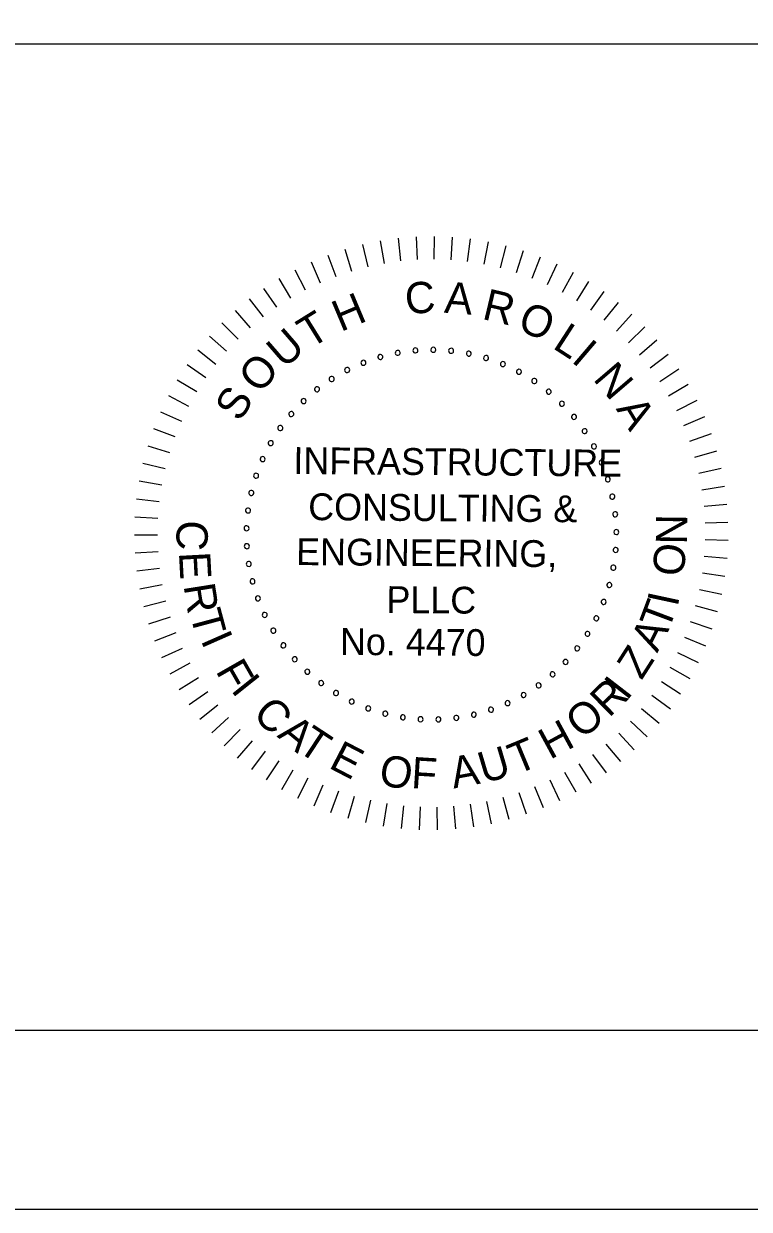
# Model space of a CAD drawing. Extents: x -133.1 to -97, y -110.1 to -88.1.
# Drawn here: x -107.945 to -105.922, y -110.103 to -106.796 of the extents above; entities that cross this region are included whole.
import ezdxf

# ---------------------------------------------------------------- set-up
doc = ezdxf.new("R2010")
doc.units = 0
for name, color, linetype in [('BR_BORDER LINES', 7, 'Continuous'), ('BR_TEXT', 7, 'Continuous'), ('Level 31', 7, 'Continuous')]:
    doc.layers.add(name, color=color, linetype=linetype)

msp = doc.modelspace()

# ---------------------------------------------------------------- linework, layer by layer
at = {"layer": 'BR_BORDER LINES'}
for p, q in [((-110.5071, -106.8526), (-105.1419, -106.8526)), ((-131.3076, -109.6027), (-97.6416, -109.6027))]:
    msp.add_line(p, q, dxfattribs=at)
at = {"layer": 'BR_TEXT'}
for p, q in [((-106.9012, -107.3945), (-106.894, -107.4577)), ((-106.8509, -107.3903), (-106.8476, -107.4539)), ((-106.8005, -107.3893), (-106.801, -107.4529)), ((-106.75, -107.3913), (-106.7544, -107.4548)), ((-106.6998, -107.3964), (-106.7081, -107.4595)), ((-107.0494, -107.4251), (-107.0308, -107.486)), ((-107.0007, -107.4119), (-106.9858, -107.4738)), ((-106.9512, -107.4017), (-106.9401, -107.4644)), ((-106.65, -107.4045), (-106.6621, -107.467)), ((-106.6007, -107.4157), (-106.6166, -107.4773)), ((-106.5523, -107.4298), (-106.5719, -107.4904)), ((-107.1439, -107.4603), (-107.1181, -107.5185)), ((-107.0972, -107.4413), (-107.0749, -107.5009)), ((-106.5048, -107.4469), (-106.528, -107.5062)), ((-107.1895, -107.4822), (-107.1601, -107.5387)), ((-106.4584, -107.4668), (-106.4852, -107.5246)), ((-106.4133, -107.4896), (-106.4436, -107.5456)), ((-107.2335, -107.5068), (-107.2008, -107.5614)), ((-106.3697, -107.515), (-106.4034, -107.569)), ((-107.276, -107.5341), (-107.24, -107.5865)), ((-106.3277, -107.543), (-106.3646, -107.5949)), ((-107.3557, -107.5961), (-107.3135, -107.6438)), ((-107.3168, -107.5638), (-107.2776, -107.614)), ((-106.2875, -107.5736), (-106.3275, -107.6231)), ((-106.2493, -107.6065), (-106.2922, -107.6535)), ((-107.3925, -107.6306), (-107.3475, -107.6756)), ((-106.2131, -107.6418), (-106.2588, -107.6861)), ((-107.4272, -107.6673), (-107.3795, -107.7095)), ((-106.1791, -107.6791), (-106.2275, -107.7205)), ((-107.4595, -107.706), (-107.4094, -107.7453)), ((-106.1475, -107.7185), (-106.1983, -107.7569)), ((-107.4895, -107.7467), (-107.437, -107.7828)), ((-106.1184, -107.7597), (-106.1714, -107.7949)), ((-107.5169, -107.7891), (-107.4623, -107.8219)), ((-106.0918, -107.8026), (-106.1469, -107.8345)), ((-107.5416, -107.8331), (-107.4852, -107.8625)), ((-106.0679, -107.847), (-106.1248, -107.8756)), ((-107.5637, -107.8785), (-107.5055, -107.9045)), ((-106.0467, -107.8929), (-106.1052, -107.9179)), ((-107.5829, -107.9252), (-107.5233, -107.9475)), ((-106.0283, -107.9399), (-106.0883, -107.9613)), ((-107.5992, -107.9729), (-107.5384, -107.9916)), ((-106.0129, -107.988), (-106.0741, -108.0057)), ((-107.6126, -108.0216), (-107.5507, -108.0366)), ((-106.0004, -108.0369), (-106.0625, -108.0508)), ((-107.623, -108.071), (-107.5604, -108.0822)), ((-105.9909, -108.0865), (-106.0538, -108.0966)), ((-107.6304, -108.121), (-107.5672, -108.1283)), ((-105.9845, -108.1366), (-106.0479, -108.1428)), ((-107.6348, -108.1712), (-107.5712, -108.1747)), ((-105.9811, -108.1869), (-106.0448, -108.1893)), ((-107.636, -108.2217), (-107.5723, -108.2213)), ((-105.9809, -108.2374), (-106.0445, -108.2359)), ((-107.6342, -108.2722), (-107.5706, -108.2678)), ((-105.9836, -108.2878), (-106.0471, -108.2824)), ((-107.6293, -108.3224), (-107.5661, -108.3142)), ((-105.9895, -108.338), (-106.0525, -108.3287)), ((-107.6213, -108.3723), (-107.5588, -108.3602)), ((-105.9984, -108.3876), (-106.0607, -108.3746)), ((-107.6103, -108.4215), (-107.5487, -108.4057)), ((-106.0103, -108.4367), (-106.0717, -108.4199)), ((-107.5964, -108.4701), (-107.5358, -108.4505)), ((-106.0252, -108.4849), (-106.0855, -108.4644)), ((-107.5795, -108.5176), (-107.5202, -108.4944)), ((-106.043, -108.5322), (-106.1019, -108.508)), ((-107.5597, -108.5641), (-107.5019, -108.5373)), ((-106.0636, -108.5783), (-106.1209, -108.5505)), ((-107.5371, -108.6092), (-107.4811, -108.579)), ((-107.5119, -108.6529), (-107.4578, -108.6193)), ((-106.087, -108.623), (-106.1426, -108.5918)), ((-106.1131, -108.6662), (-106.1667, -108.6317)), ((-107.484, -108.695), (-107.4321, -108.6582)), ((-106.1418, -108.7077), (-106.1931, -108.6701)), ((-107.4536, -108.7353), (-107.404, -108.6954)), ((-106.173, -108.7475), (-106.2219, -108.7067)), ((-107.4208, -108.7737), (-107.3737, -108.7308)), ((-106.2065, -108.7852), (-106.2529, -108.7416)), ((-107.3857, -108.81), (-107.3413, -108.7643)), ((-106.2423, -108.8208), (-106.2859, -108.7744)), ((-107.3485, -108.8441), (-107.307, -108.7958)), ((-106.2801, -108.8542), (-106.3208, -108.8053)), ((-107.3092, -108.8759), (-107.2708, -108.8251)), ((-107.2681, -108.9052), (-107.2328, -108.8522)), ((-106.32, -108.8852), (-106.3576, -108.8339)), ((-107.2253, -108.9319), (-107.1933, -108.8769)), ((-106.4049, -108.9397), (-106.436, -108.8841)), ((-106.3616, -108.9138), (-106.3961, -108.8602)), ((-107.1809, -108.956), (-107.1523, -108.8991)), ((-107.1352, -108.9774), (-107.1101, -108.9188)), ((-106.4498, -108.963), (-106.4774, -108.9056)), ((-107.0882, -108.9959), (-107.0668, -108.9359)), ((-107.0402, -109.0115), (-107.0225, -108.9504)), ((-106.5432, -109.001), (-106.5637, -108.9408)), ((-106.4959, -108.9834), (-106.52, -108.9245)), ((-106.9913, -109.0242), (-106.9773, -108.962)), ((-106.9418, -109.0338), (-106.9316, -108.971)), ((-106.8918, -109.0404), (-106.8854, -108.9771)), ((-106.8414, -109.044), (-106.8389, -108.9804)), ((-106.7909, -109.0445), (-106.7923, -108.9808)), ((-106.7405, -109.0419), (-106.7458, -108.9784)), ((-106.6903, -109.0362), (-106.6995, -108.9732)), ((-106.6406, -109.0275), (-106.6536, -108.9651)), ((-106.5915, -109.0157), (-106.6083, -108.9543))]:
    msp.add_line(p, q, dxfattribs=at)
for centre, start, end in [((-106.9506, -107.7254), 16.1422, 196.1422), ((-106.9506, -107.7254), 196.1422, 16.1422), ((-106.9021, -107.714), 10.6038, 190.6038), ((-106.9021, -107.714), 190.6038, 10.6038), ((-106.8527, -107.7073), 5.0653, 185.0653), ((-106.8527, -107.7073), 185.0653, 5.0653), ((-106.8029, -107.7054), 359.5268, 179.5268), ((-106.8029, -107.7054), 179.5268, 359.5268), ((-106.7531, -107.7083), 173.9884, 353.9884), ((-106.7531, -107.7083), 353.9884, 173.9884), ((-106.7039, -107.716), 168.4499, 348.4499), ((-106.7039, -107.716), 348.4499, 168.4499), ((-106.6557, -107.7285), 162.9114, 342.9114), ((-106.6557, -107.7285), 342.9114, 162.9114), ((-107.0431, -107.762), 27.2191, 207.2191), ((-107.0431, -107.762), 207.2191, 27.2191), ((-106.9977, -107.7415), 21.6807, 201.6807), ((-106.9977, -107.7415), 201.6807, 21.6807), ((-106.6088, -107.7455), 157.373, 337.373), ((-106.6088, -107.7455), 337.373, 157.373), ((-106.5639, -107.7669), 331.8345, 151.8345), ((-107.0864, -107.7869), 32.7576, 212.7576), ((-107.0864, -107.7869), 212.7576, 32.7576), ((-106.5639, -107.7669), 151.8345, 331.8345), ((-106.5212, -107.7926), 146.2961, 326.2961), ((-106.5212, -107.7926), 326.2961, 146.2961), ((-107.127, -107.8157), 38.2961, 218.2961), ((-107.127, -107.8157), 218.2961, 38.2961), ((-106.4811, -107.8223), 140.7576, 320.7576), ((-106.4811, -107.8223), 320.7576, 140.7576), ((-107.1646, -107.8484), 43.8345, 223.8345), ((-107.1646, -107.8484), 223.8345, 43.8345), ((-106.4442, -107.8558), 135.2191, 315.2191), ((-106.4442, -107.8558), 315.2191, 135.2191), ((-107.1989, -107.8845), 49.373, 229.373), ((-107.1989, -107.8845), 229.373, 49.373), ((-106.4106, -107.8926), 129.6807, 309.6807), ((-106.4106, -107.8926), 309.6807, 129.6807), ((-107.2296, -107.9238), 54.9114, 234.9114), ((-107.2296, -107.9238), 234.9114, 54.9114), ((-106.3808, -107.9325), 124.1422, 304.1422), ((-106.3808, -107.9325), 304.1422, 124.1422), ((-107.2563, -107.9659), 60.4499, 240.4499), ((-107.2563, -107.9659), 240.4499, 60.4499), ((-106.3549, -107.9751), 118.6038, 298.6038), ((-106.3549, -107.9751), 298.6038, 118.6038), ((-107.2788, -108.0103), 65.9884, 245.9884), ((-107.2788, -108.0103), 245.9884, 65.9884), ((-106.3333, -108.02), 113.0653, 293.0653), ((-106.3333, -108.02), 293.0653, 113.0653), ((-107.297, -108.0567), 71.5268, 251.5268), ((-107.297, -108.0567), 251.5268, 71.5268), ((-106.3161, -108.0668), 107.5268, 287.5268), ((-106.3161, -108.0668), 287.5268, 107.5268), ((-107.3106, -108.1047), 77.0653, 257.0653), ((-107.3106, -108.1047), 257.0653, 77.0653), ((-106.3035, -108.115), 101.9884, 281.9884), ((-106.3035, -108.115), 281.9884, 101.9884), ((-107.3195, -108.1537), 82.6038, 262.6038), ((-107.3195, -108.1537), 262.6038, 82.6038), ((-106.2956, -108.1642), 96.4499, 276.4499), ((-106.2956, -108.1642), 276.4499, 96.4499), ((-107.3236, -108.2034), 88.1422, 268.1422), ((-107.3236, -108.2034), 268.1422, 88.1422), ((-106.2925, -108.2139), 90.9114, 270.9114), ((-106.2925, -108.2139), 270.9114, 90.9114), ((-107.3229, -108.2532), 93.6807, 273.6807), ((-107.3229, -108.2532), 273.6807, 93.6807), ((-106.2942, -108.2637), 85.373, 265.373), ((-106.2942, -108.2637), 265.373, 85.373), ((-107.3174, -108.3027), 99.2191, 279.2191), ((-107.3174, -108.3027), 279.2191, 99.2191), ((-106.3007, -108.3131), 79.8345, 259.8345), ((-106.3007, -108.3131), 259.8345, 79.8345), ((-107.3071, -108.3515), 104.7576, 284.7576), ((-107.3071, -108.3515), 284.7576, 104.7576), ((-106.312, -108.3617), 74.2961, 254.2961), ((-106.312, -108.3617), 254.2961, 74.2961), ((-107.2922, -108.399), 110.2961, 290.2961), ((-107.2922, -108.399), 290.2961, 110.2961), ((-106.3279, -108.4089), 68.7576, 248.7576), ((-106.3279, -108.4089), 248.7576, 68.7576), ((-107.2728, -108.4449), 115.8345, 295.8345), ((-107.2728, -108.4449), 295.8345, 115.8345), ((-106.3483, -108.4544), 63.2191, 243.2191), ((-106.3483, -108.4544), 243.2191, 63.2191), ((-107.249, -108.4887), 121.373, 301.373), ((-107.249, -108.4887), 301.373, 121.373), ((-106.3729, -108.4977), 57.6807, 237.6807), ((-106.3729, -108.4977), 237.6807, 57.6807), ((-107.2211, -108.53), 126.9114, 306.9114), ((-107.2211, -108.53), 306.9114, 126.9114), ((-106.4016, -108.5384), 52.1422, 232.1422), ((-106.4016, -108.5384), 232.1422, 52.1422), ((-107.1894, -108.5684), 132.4499, 312.4499), ((-107.1894, -108.5684), 312.4499, 132.4499), ((-106.4342, -108.5761), 46.6038, 226.6038), ((-106.4342, -108.5761), 226.6038, 46.6038), ((-107.1541, -108.6036), 137.9884, 317.9884), ((-107.1541, -108.6036), 317.9884, 137.9884), ((-106.4702, -108.6106), 41.0653, 221.0653), ((-106.4702, -108.6106), 221.0653, 41.0653), ((-107.1156, -108.6352), 143.5268, 323.5268), ((-107.1156, -108.6352), 323.5268, 143.5268), ((-106.5093, -108.6414), 35.5268, 215.5268), ((-106.5093, -108.6414), 215.5268, 35.5268), ((-107.0742, -108.6629), 149.0653, 329.0653), ((-107.0742, -108.6629), 329.0653, 149.0653), ((-107.0303, -108.6865), 154.6038, 334.6038), ((-107.0303, -108.6865), 334.6038, 154.6038), ((-106.5957, -108.691), 24.4499, 204.4499), ((-106.5513, -108.6683), 29.9884, 209.9884), ((-106.5513, -108.6683), 209.9884, 29.9884), ((-106.9843, -108.7058), 160.1422, 340.1422), ((-106.9843, -108.7058), 340.1422, 160.1422), ((-106.9367, -108.7205), 165.6807, 345.6807), ((-106.9367, -108.7205), 345.6807, 165.6807), ((-106.6899, -108.7231), 13.373, 193.373), ((-106.642, -108.7093), 18.9114, 198.9114), ((-106.642, -108.7093), 198.9114, 18.9114), ((-106.5957, -108.691), 204.4499, 24.4499), ((-106.8879, -108.7306), 171.2191, 351.2191), ((-106.8879, -108.7306), 351.2191, 171.2191), ((-106.8384, -108.7359), 356.7576, 176.7576), ((-106.8384, -108.7359), 176.7576, 356.7576), ((-106.7885, -108.7364), 2.2961, 182.2961), ((-106.7885, -108.7364), 182.2961, 2.2961), ((-106.7389, -108.7321), 7.8345, 187.8345), ((-106.7389, -108.7321), 187.8345, 7.8345), ((-106.6899, -108.7231), 193.373, 13.373)]:
    msp.add_arc(centre, 0.00701, start, end, dxfattribs=at)
at = {"layer": 'Level 31'}
msp.add_lwpolyline([(-133.1409, -110.1026), (-97.141, -110.1026), (-97.141, -88.1026), (-133.1409, -88.1026)], close=True, dxfattribs=at)

# ---------------------------------------------------------------- texts
at = {"layer": 'BR_TEXT'}
for s, height, rotation, p in [('C', 0.0872, 4.7281, (-106.8784, -107.6069)), ('A', 0.0872, 355.6981, (-106.7739, -107.6019)), ('H', 0.0872, 22.7882, (-107.0612, -107.6563)), ('R', 0.0872, 346.6681, (-106.6696, -107.6189)), ('T', 0.0872, 31.8182, (-107.1461, -107.7039)), ('O', 0.0872, 337.638, (-106.5719, -107.6487)), ('U', 0.0872, 40.8482, (-107.2194, -107.76)), ('L', 0.0872, 327.108, (-106.4731, -107.6992)), ('I', 0.0872, 319.578, (-106.4205, -107.737)), ('O', 0.0872, 49.8782, (-107.2864, -107.831)), ('N', 0.0872, 310.548, (-106.3597, -107.7878)), ('S', 0.0872, 58.9083, (-107.3418, -107.9092)), ('A', 0.0872, 301.5179, (-106.2946, -107.8702)), ('INFRASTRUCTURE', 0.074771, 359.5268, (-107.1932, -108.0517)), ('CONSULTING &', 0.074771, 359.5268, (-107.1519, -108.1804)), ('C', 0.0872, 267.025, (-107.5168, -108.1792)), ('N', 0.0872, 89.2085, (-106.0953, -108.2489)), ('ENGINEERING,', 0.074771, 359.5268, (-107.1855, -108.3058)), ('O', 0.0872, 83.2085, (-106.1064, -108.3404)), ('E', 0.0872, 273.025, (-107.5124, -108.2707)), ('R', 0.0872, 279.025, (-107.4996, -108.363)), ('PLLC', 0.07477, 359.5268, (-106.9338, -108.4394)), ('I', 0.0872, 77.9093, (-106.1219, -108.4247)), ('T', 0.0872, 285.025, (-107.4822, -108.4418)), ('T', 0.0872, 69.3954, (-106.1476, -108.4921)), ('No. 4470', 0.07477, 359.5268, (-107.0633, -108.5563)), ('A', 0.0872, 63.3954, (-106.1784, -108.5525)), ('I', 0.0872, 293.7713, (-107.4525, -108.5149)), ('Z', 0.0872, 57.3954, (-106.2222, -108.6288)), ('F', 0.0872, 299.7713, (-107.4113, -108.601)), ('I', 0.0872, 308.5268, (-107.3692, -108.6548)), ('I', 0.0872, 52.3339, (-106.2633, -108.6865)), ('R', 0.0872, 44.5268, (-106.3127, -108.7338)), ('C', 0.0872, 314.5268, (-107.3099, -108.7249)), ('O', 0.0872, 38.5268, (-106.3893, -108.7938)), ('A', 0.0872, 320.5268, (-107.2407, -108.7835)), ('T', 0.0872, 326.5268, (-107.1863, -108.822)), ('H', 0.0872, 28.5268, (-106.4774, -108.8498)), ('T', 0.0872, 22.5268, (-106.5706, -108.8915)), ('E', 0.0872, 332.5268, (-107.0977, -108.8698)), ('U', 0.0872, 16.5268, (-106.6623, -108.9159)), ('O', 0.0872, 350.5268, (-106.9576, -108.9186)), ('F', 0.0872, 356.5268, (-106.8661, -108.9278)), ('A', 0.0872, 10.5268, (-106.7462, -108.9294))]:
    msp.add_text(s, height=height, rotation=rotation, dxfattribs=at).set_placement(p)

doc.saveas('drawing.dxf')
